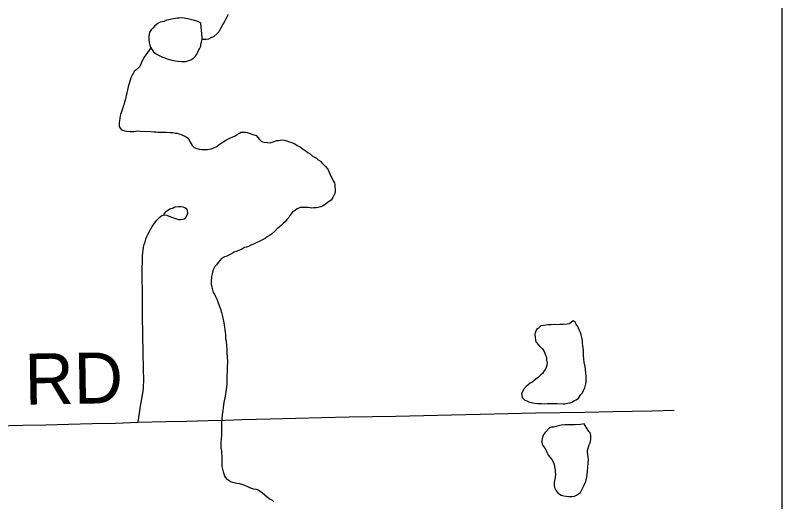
# Model space of a CAD drawing. Extents: x -11.4 to 84.1, y 11.1 to 59.
# Drawn here: x 32.31 to 33.165, y 45.216 to 45.758 of the extents above; entities that cross this region are included whole.
import ezdxf

# ---------------------------------------------------------------- set-up
doc = ezdxf.new("R2010")
doc.units = 0
for name, color, linetype in [('GM_X_Minor_Lake', 7, 'Continuous'), ('GM_X_Minor_River', 7, 'Continuous'), ('GM_X_Township_Road', 7, 'Continuous'), ('GM_X_Township_Road_Text', 7, 'Continuous'), ('SH_Data', 7, 'Continuous')]:
    doc.layers.add(name, color=color, linetype=linetype)

msp = doc.modelspace()

# ---------------------------------------------------------------- linework, layer by layer
at = {"layer": 'GM_X_Minor_Lake'}
for points in [[(32.51723, 45.74913), (32.51684, 45.74951), (32.51723, 45.74913), (32.51378, 45.75098), (32.50996, 45.75206), (32.50424, 45.75349), (32.49853, 45.75453), (32.4951, 45.75485), (32.49283, 45.75482), (32.49093, 45.75479), (32.48865, 45.75437), (32.48449, 45.75354), (32.48147, 45.75273), (32.47881, 45.75231), (32.47618, 45.75112), (32.4739, 45.7507), (32.47163, 45.75029), (32.469, 45.74872), (32.46563, 45.74601), (32.46376, 45.74407), (32.46152, 45.74175), (32.45966, 45.73906), (32.45899, 45.73373), (32.45904, 45.73107), (32.45948, 45.72765), (32.46029, 45.72462), (32.46108, 45.72236)], [(32.51723, 45.74913), (32.51684, 45.74951), (32.51723, 45.74913), (32.51378, 45.75098), (32.50996, 45.75206), (32.50424, 45.75349), (32.49853, 45.75453), (32.4951, 45.75485), (32.49283, 45.75482), (32.49093, 45.75479), (32.48865, 45.75437), (32.48449, 45.75354), (32.48147, 45.75273), (32.47881, 45.75231), (32.47618, 45.75112), (32.4739, 45.7507), (32.47163, 45.75029), (32.469, 45.74872), (32.46563, 45.74601), (32.46376, 45.74407), (32.46152, 45.74175), (32.45966, 45.73906), (32.45899, 45.73373), (32.45904, 45.73107), (32.45948, 45.72765), (32.46029, 45.72462), (32.46108, 45.72236), (32.46187, 45.72047), (32.46421, 45.71708), (32.46729, 45.71485), (32.47074, 45.71301), (32.47418, 45.71116), (32.47686, 45.71045), (32.47953, 45.70935), (32.4822, 45.70863), (32.48487, 45.70791), (32.4883, 45.70721), (32.49173, 45.70689), (32.49554, 45.70619), (32.49858, 45.70624), (32.50047, 45.70627), (32.50274, 45.70707), (32.50576, 45.70826), (32.50914, 45.71059), (32.51101, 45.71215), (32.51249, 45.71445), (32.51432, 45.71867), (32.51543, 45.72058), (32.5169, 45.72327), (32.51725, 45.72518), (32.51797, 45.72785), (32.51867, 45.73128), (32.51864, 45.73319), (32.51723, 45.74913)], [(32.46108, 45.72236), (32.46187, 45.72047), (32.46421, 45.71708), (32.46729, 45.71485), (32.47074, 45.71301), (32.47418, 45.71116), (32.47686, 45.71045), (32.47953, 45.70935), (32.4822, 45.70863), (32.48487, 45.70791), (32.4883, 45.70721), (32.49173, 45.70689), (32.49554, 45.70619), (32.49858, 45.70624), (32.50047, 45.70627), (32.50274, 45.70707), (32.50576, 45.70826), (32.50914, 45.71059), (32.51101, 45.71215), (32.51249, 45.71445), (32.51432, 45.71867), (32.51543, 45.72058), (32.5169, 45.72327), (32.51725, 45.72518), (32.51797, 45.72785), (32.51867, 45.73128), (32.51864, 45.73319), (32.51723, 45.74913)], [(32.93263, 45.41713), (32.9285, 45.41402), (32.92585, 45.41359), (32.9213, 45.41314), (32.91788, 45.41308), (32.91484, 45.41303), (32.91142, 45.41336), (32.90801, 45.41292), (32.90459, 45.41286), (32.90194, 45.41244), (32.89929, 45.41202), (32.89664, 45.41159), (32.89364, 45.40888), (32.89176, 45.40771), (32.89031, 45.40388), (32.88996, 45.40198), (32.89001, 45.39894), (32.89045, 45.39552), (32.89124, 45.39363), (32.89511, 45.38913), (32.8982, 45.38614), (32.90015, 45.38313), (32.90094, 45.38124), (32.90174, 45.37897), (32.90292, 45.37671), (32.90297, 45.37329), (32.9034, 45.37064), (32.90307, 45.36759), (32.90199, 45.36415), (32.90013, 45.36145), (32.89828, 45.35876), (32.89641, 45.35721), (32.89342, 45.35412), (32.89079, 45.35218), (32.88854, 45.35062), (32.88667, 45.34907), (32.88479, 45.3479), (32.88217, 45.34557), (32.88029, 45.34402), (32.87731, 45.34093), (32.87658, 45.33902), (32.87511, 45.33633), (32.87514, 45.33443), (32.87556, 45.33177), (32.87865, 45.32878), (32.88094, 45.32806), (32.88324, 45.32696)], [(32.93263, 45.41713), (32.9285, 45.41402), (32.92585, 45.41359), (32.9213, 45.41314), (32.91788, 45.41308), (32.91484, 45.41303), (32.91142, 45.41336), (32.90801, 45.41292), (32.90459, 45.41286), (32.90194, 45.41244), (32.89929, 45.41202), (32.89664, 45.41159), (32.89364, 45.40888), (32.89176, 45.40771), (32.89031, 45.40388), (32.88996, 45.40198), (32.89001, 45.39894), (32.89045, 45.39552), (32.89124, 45.39363), (32.89511, 45.38913), (32.8982, 45.38614), (32.90015, 45.38313), (32.90094, 45.38124), (32.90174, 45.37897), (32.90292, 45.37671), (32.90297, 45.37329), (32.9034, 45.37064), (32.90307, 45.36759), (32.90199, 45.36415), (32.90013, 45.36145), (32.89828, 45.35876), (32.89641, 45.35721), (32.89342, 45.35412), (32.89079, 45.35218), (32.88854, 45.35062), (32.88667, 45.34907), (32.88479, 45.3479), (32.88217, 45.34557), (32.88029, 45.34402), (32.87731, 45.34093), (32.87658, 45.33902), (32.87511, 45.33633), (32.87514, 45.33443), (32.87556, 45.33177), (32.87865, 45.32878), (32.88094, 45.32806), (32.88324, 45.32696), (32.88591, 45.32624), (32.88934, 45.32553), (32.89315, 45.32522), (32.89732, 45.32528), (32.90036, 45.32495), (32.90378, 45.32501), (32.9072, 45.32507), (32.90986, 45.32511), (32.91214, 45.32515), (32.91479, 45.32519), (32.92126, 45.32492), (32.92315, 45.32495), (32.92619, 45.32538), (32.92884, 45.3258), (32.9311, 45.3266), (32.93411, 45.32855), (32.936, 45.32934), (32.93862, 45.33129), (32.94122, 45.33513), (32.94308, 45.33706), (32.94418, 45.33974), (32.94565, 45.34281), (32.94636, 45.34548), (32.94707, 45.34854), (32.94701, 45.35196), (32.94695, 45.35538), (32.94689, 45.35918), (32.94645, 45.3626), (32.946, 45.36677), (32.9448, 45.37056), (32.94435, 45.37511), (32.94429, 45.37815), (32.94426, 45.38043), (32.94422, 45.38233), (32.94419, 45.38423), (32.94377, 45.38689), (32.94334, 45.38954), (32.94291, 45.39258), (32.94287, 45.39524), (32.94243, 45.39866), (32.94162, 45.40168), (32.94082, 45.40433), (32.93925, 45.40735), (32.93766, 45.41113), (32.9361, 45.41376), (32.93493, 45.41565), (32.93263, 45.41713)], [(32.88324, 45.32696), (32.88591, 45.32624), (32.88934, 45.32553), (32.89315, 45.32522), (32.89732, 45.32528), (32.90036, 45.32495), (32.90378, 45.32501), (32.9072, 45.32507), (32.90986, 45.32511), (32.91214, 45.32515), (32.91479, 45.32519), (32.92126, 45.32492), (32.92315, 45.32495), (32.92619, 45.32538), (32.92884, 45.3258), (32.9311, 45.3266), (32.93411, 45.32855), (32.936, 45.32934), (32.93862, 45.33129), (32.94122, 45.33513), (32.94308, 45.33706), (32.94418, 45.33974), (32.94565, 45.34281), (32.94636, 45.34548), (32.94707, 45.34854), (32.94701, 45.35196), (32.94695, 45.35538), (32.94689, 45.35918), (32.94645, 45.3626), (32.946, 45.36677), (32.9448, 45.37056), (32.94435, 45.37511), (32.94429, 45.37815), (32.94426, 45.38043), (32.94422, 45.38233), (32.94419, 45.38423), (32.94377, 45.38689), (32.94334, 45.38954), (32.94291, 45.39258), (32.94287, 45.39524), (32.94243, 45.39866), (32.94162, 45.40168), (32.94082, 45.40433), (32.93925, 45.40735), (32.93766, 45.41113), (32.9361, 45.41376), (32.93493, 45.41565), (32.93263, 45.41713)], [(32.9448, 45.30249), (32.94064, 45.30166), (32.93494, 45.30156), (32.93, 45.30148), (32.92621, 45.30142), (32.92317, 45.30137), (32.91938, 45.30093), (32.91635, 45.30012), (32.91332, 45.29969), (32.91068, 45.29888), (32.9084, 45.29885), (32.90613, 45.29805), (32.90128, 45.29303), (32.89979, 45.2911), (32.89833, 45.28766), (32.89798, 45.28575), (32.89763, 45.28384), (32.89767, 45.28194), (32.89808, 45.27967), (32.89964, 45.27741), (32.9012, 45.27515), (32.90238, 45.27289), (32.90357, 45.26987), (32.90513, 45.26723), (32.90668, 45.26535), (32.90862, 45.26273), (32.91058, 45.25934), (32.91138, 45.25707), (32.91179, 45.25479), (32.91221, 45.2529), (32.91262, 45.251), (32.91266, 45.24872), (32.9127, 45.24606), (32.91238, 45.24263), (32.91168, 45.2392), (32.91133, 45.23729), (32.91138, 45.23425), (32.9118, 45.2316), (32.91376, 45.22783), (32.91532, 45.22557), (32.91725, 45.22408), (32.91917, 45.22297), (32.92222, 45.22226), (32.92488, 45.22192), (32.92792, 45.22159), (32.93096, 45.22164), (32.93399, 45.22207), (32.93626, 45.22287), (32.94076, 45.22599), (32.9426, 45.22982), (32.94481, 45.23404), (32.94664, 45.23825), (32.94734, 45.24168), (32.94804, 45.2455), (32.94872, 45.24969), (32.94903, 45.25426), (32.94933, 45.25883), (32.94965, 45.26264), (32.94922, 45.26567), (32.94879, 45.26833), (32.94875, 45.27099), (32.94872, 45.27289), (32.94943, 45.27556), (32.95051, 45.279), (32.95161, 45.2813), (32.95196, 45.28321), (32.95231, 45.28512), (32.95228, 45.28702), (32.95225, 45.28892), (32.95182, 45.29195), (32.95026, 45.29383), (32.94825, 45.29702)], [(32.94825, 45.29702), (32.9448, 45.30249)]]:
    msp.add_lwpolyline(points, dxfattribs=at)
at = {"layer": 'GM_X_Minor_River'}
for points in [[(32.54746, 45.75876), (32.54599, 45.75569), (32.54451, 45.753)], [(32.54451, 45.753), (32.54304, 45.75032), (32.54156, 45.74801), (32.54046, 45.74571), (32.53862, 45.74226), (32.53714, 45.73957), (32.53527, 45.73764), (32.53116, 45.73377), (32.5289, 45.73297), (32.5255, 45.7314), (32.52285, 45.73097), (32.51855, 45.7307)], [(32.46136, 45.7217), (32.45367, 45.71121), (32.4511, 45.70622), (32.44891, 45.70086), (32.44442, 45.6966), (32.44255, 45.69505), (32.44144, 45.69313), (32.43997, 45.69045), (32.43887, 45.68815), (32.43599, 45.67821), (32.43529, 45.67478), (32.43459, 45.67134), (32.43353, 45.66676), (32.43282, 45.66333), (32.43172, 45.66103), (32.43101, 45.65798), (32.43029, 45.65606), (32.42957, 45.65377), (32.42885, 45.65148), (32.42812, 45.64918), (32.4274, 45.64727), (32.42705, 45.64536), (32.42671, 45.64308), (32.42637, 45.64041), (32.42602, 45.6385), (32.42607, 45.63584), (32.4261, 45.63394), (32.42689, 45.63205), (32.42844, 45.63017), (32.43226, 45.6291), (32.43454, 45.62875), (32.43835, 45.62844), (32.44214, 45.6285), (32.44593, 45.62894), (32.44974, 45.62862), (32.45544, 45.62834), (32.45733, 45.62875), (32.46114, 45.62843), (32.46456, 45.62811), (32.46722, 45.62815), (32.46913, 45.62742), (32.47217, 45.62747), (32.47445, 45.62751), (32.47672, 45.62755), (32.47862, 45.62758), (32.48281, 45.62726), (32.48585, 45.62731), (32.48889, 45.6266), (32.49079, 45.62663), (32.49271, 45.62591), (32.495, 45.62518), (32.50074, 45.62224), (32.50343, 45.62038), (32.50501, 45.6166), (32.50619, 45.61472), (32.50736, 45.61284), (32.50967, 45.61059), (32.51273, 45.6095), (32.5154, 45.60878), (32.51807, 45.60845), (32.52073, 45.60811), (32.52263, 45.60814), (32.52453, 45.60817), (32.52642, 45.60859), (32.52869, 45.609), (32.53171, 45.6102), (32.5351, 45.61177), (32.53773, 45.61371), (32.54073, 45.61605), (32.54486, 45.61877), (32.54939, 45.62075), (32.55278, 45.62233), (32.55466, 45.62312), (32.55767, 45.62507), (32.5603, 45.62663), (32.56219, 45.62743), (32.56409, 45.62746), (32.56675, 45.6275), (32.56865, 45.62715), (32.57094, 45.62643), (32.574, 45.62534), (32.57629, 45.62461), (32.57896, 45.6239), (32.58052, 45.62164), (32.58207, 45.61977), (32.58477, 45.61715), (32.58782, 45.61644), (32.59429, 45.61578), (32.59882, 45.61738), (32.60184, 45.61819), (32.60412, 45.61823), (32.60715, 45.61904), (32.61019, 45.6187), (32.61324, 45.61799), (32.61554, 45.61689), (32.61745, 45.61654), (32.62203, 45.61472), (32.62472, 45.61286), (32.62779, 45.61139), (32.6301, 45.60953), (32.6324, 45.60804)], [(32.6324, 45.60804), (32.63471, 45.60656), (32.63663, 45.60507), (32.63893, 45.60359), (32.64125, 45.60134), (32.64393, 45.59987), (32.64623, 45.59876), (32.64816, 45.59689), (32.65047, 45.59541), (32.65202, 45.59353), (32.65395, 45.59166), (32.65626, 45.58942), (32.65897, 45.58642), (32.65978, 45.58377), (32.66096, 45.58113), (32.66214, 45.57849), (32.66332, 45.57661), (32.66489, 45.57321), (32.66607, 45.57095), (32.66648, 45.56905), (32.66652, 45.56639), (32.66694, 45.56412), (32.66699, 45.56108), (32.66665, 45.55917), (32.66555, 45.55687), (32.66444, 45.55495), (32.66259, 45.55188), (32.65958, 45.54993), (32.6547, 45.54642), (32.65283, 45.54525), (32.65094, 45.54446), (32.64791, 45.54365), (32.64564, 45.54323), (32.64336, 45.5432), (32.64109, 45.54278), (32.63728, 45.54348), (32.63462, 45.54381), (32.63272, 45.54378), (32.63006, 45.54374), (32.62778, 45.5437), (32.62477, 45.54213), (32.62177, 45.5398), (32.61951, 45.53862), (32.61802, 45.5367), (32.61654, 45.53477), (32.61543, 45.53247), (32.6132, 45.53015), (32.61133, 45.52784), (32.60909, 45.5259), (32.60685, 45.52358), (32.60498, 45.52203), (32.60198, 45.51932), (32.59974, 45.51738), (32.596, 45.5139), (32.59374, 45.51234), (32.59111, 45.51078), (32.58923, 45.50961), (32.5866, 45.50804), (32.58283, 45.50608), (32.57869, 45.50411), (32.57529, 45.50253), (32.57303, 45.50174), (32.5704, 45.50017), (32.56813, 45.49937), (32.56586, 45.49895), (32.56361, 45.4974), (32.55945, 45.49581), (32.55644, 45.49462), (32.55417, 45.49382), (32.55229, 45.49265), (32.54966, 45.49109), (32.54627, 45.48951), (32.54362, 45.4887), (32.54023, 45.48675), (32.53651, 45.4825), (32.53465, 45.47981), (32.53279, 45.47788), (32.53168, 45.47558), (32.53059, 45.4729), (32.52988, 45.46984), (32.52917, 45.46679), (32.52883, 45.46488), (32.52848, 45.46298), (32.52852, 45.46032), (32.52856, 45.45803), (32.52937, 45.45501), (32.53018, 45.45198), (32.53099, 45.44895), (32.53256, 45.44631), (32.53335, 45.44442), (32.53492, 45.44141), (32.53611, 45.43838), (32.5377, 45.43423), (32.5389, 45.43045), (32.5401, 45.42666), (32.54091, 45.42363), (32.54172, 45.42061), (32.54254, 45.41682), (32.54299, 45.41302), (32.54341, 45.41037), (32.54384, 45.40733)], [(32.54384, 45.40733), (32.54427, 45.40467), (32.5447, 45.40164), (32.54474, 45.39936), (32.54477, 45.39708), (32.54519, 45.39518), (32.54522, 45.3929), (32.54564, 45.39101), (32.54567, 45.38911), (32.5461, 45.38607), (32.54617, 45.38189), (32.54663, 45.37734), (32.54672, 45.37163), (32.54644, 45.36554), (32.54653, 45.3606), (32.54621, 45.35679), (32.54626, 45.35375), (32.54593, 45.3507), (32.54599, 45.34728), (32.54567, 45.34348), (32.54433, 45.33319), (32.54292, 45.32632), (32.54188, 45.3206), (32.54156, 45.31717), (32.54086, 45.31298), (32.54056, 45.30841), (32.54026, 45.30384), (32.53997, 45.29851), (32.54004, 45.29433), (32.54011, 45.28977), (32.53981, 45.28558), (32.53948, 45.28253), (32.53953, 45.27949), (32.53959, 45.27569), (32.54003, 45.27189), (32.54007, 45.26961), (32.54049, 45.26734), (32.54052, 45.26544), (32.54057, 45.26278), (32.54062, 45.25974), (32.54065, 45.25745), (32.5407, 45.25479), (32.54112, 45.25214), (32.54193, 45.24911), (32.54273, 45.24684), (32.54354, 45.24419), (32.54548, 45.24156), (32.54817, 45.2397), (32.55009, 45.23821), (32.55239, 45.23749), (32.55429, 45.23714), (32.55734, 45.23643), (32.56038, 45.2361), (32.56382, 45.23502), (32.5665, 45.23392), (32.56841, 45.23319), (32.57147, 45.23172), (32.57568, 45.22989), (32.57873, 45.22956), (32.58102, 45.22883), (32.58371, 45.22698), (32.58562, 45.22587), (32.59141, 45.22064), (32.59449, 45.21841), (32.59678, 45.21731), (32.59871, 45.21544)]]:
    msp.add_lwpolyline(points, dxfattribs=at)
at = {"layer": 'GM_X_Township_Road'}
for points in [[(32.44708, 45.30429), (32.44954, 45.32005), (32.45204, 45.33493), (32.45266, 45.3389), (32.45295, 45.34231), (32.45318, 45.34521), (32.45341, 45.34982), (32.45288, 45.38088), (32.45252, 45.40193), (32.45216, 45.42298), (32.45192, 45.44622), (32.45167, 45.46946), (32.45193, 45.48993), (32.45221, 45.49306), (32.45268, 45.49617), (32.45326, 45.49925), (32.45401, 45.5023), (32.45487, 45.50532), (32.45587, 45.5083), (32.457, 45.51123), (32.45824, 45.51411), (32.45966, 45.51693), (32.46118, 45.51968), (32.46279, 45.52235), (32.46455, 45.52496), (32.46639, 45.52749), (32.46805, 45.52948), (32.46981, 45.53136), (32.47165, 45.53315), (32.4736, 45.53482), (32.47638, 45.53543), (32.47896, 45.53517), (32.48326, 45.53332), (32.48782, 45.53174), (32.49232, 45.53041), (32.49489, 45.53008), (32.4984, 45.53087), (32.50039, 45.53253), (32.5019, 45.53497), (32.50263, 45.53748), (32.50224, 45.54039), (32.50151, 45.54185), (32.49999, 45.54304), (32.49761, 45.5441), (32.49496, 45.54456), (32.49199, 45.54449), (32.48795, 45.54383), (32.48604, 45.54304), (32.48234, 45.54165), (32.47876, 45.53927), (32.47738, 45.53835), (32.47526, 45.5357)], [(32.28734, 45.30025), (32.3184, 45.30094), (32.34398, 45.30149), (32.36955, 45.30205), (32.39566, 45.30274), (32.42177, 45.30342), (32.44708, 45.30429), (32.4781, 45.30502), (32.50164, 45.30558), (32.52518, 45.30614), (32.5442, 45.30672), (32.56322, 45.3073), (32.59428, 45.30811), (32.62297, 45.30885), (32.65167, 45.3096), (32.68273, 45.31021), (32.70879, 45.31073), (32.73485, 45.31124), (32.76592, 45.31195), (32.79698, 45.31266), (32.81286, 45.31302), (32.82873, 45.31338), (32.85979, 45.31398), (32.89086, 45.31459), (32.91824, 45.31512), (32.94562, 45.31566), (32.97669, 45.31626), (32.99856, 45.31668), (33.02044, 45.31711), (33.0454, 45.31756)]]:
    msp.add_lwpolyline(points, dxfattribs=at)
at = {"layer": 'SH_Data'}
msp.add_line((33.16529, 47.54828), (33.16529, 40.54828), dxfattribs=at)

# ---------------------------------------------------------------- texts
at = {"layer": 'GM_X_Township_Road_Text'}
msp.add_text('RD', height=0.056818, rotation=0.96738, dxfattribs=at).set_placement((32.32086, 45.32386))

doc.saveas('drawing.dxf')
